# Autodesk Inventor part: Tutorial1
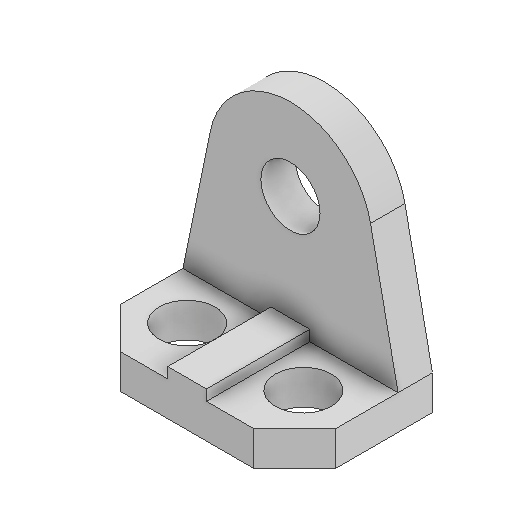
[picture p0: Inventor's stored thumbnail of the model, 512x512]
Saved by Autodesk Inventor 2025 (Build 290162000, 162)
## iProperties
Created: 2021-03
Part Number: Tutorial1
Material: Generic
Document SubType Name: Modeling
Designer: ASUS Laptop
Density: 1 g/cm^3
Appearance: Default
Author: ASUS Laptop
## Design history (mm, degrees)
sketch "Sketch1"
  geometry: L1 (0, 0)-(-200, 0); L2 (-200, 0)-(-200, 90); L3 (-200, 90)-(-162, 128); L4 (-162, 128)-(-38, 128); L5 (-38, 128)-(0, 90); L6 (0, 90)-(0, 0); L7 (-154, 74)-(-31.817, 74); C1 r 26 at (-154, 74); C2 r 26 at (-46, 74); 1 further point
  constraints: 14 end point, 2 centre point, 2 horizontal, 2 parallel, 2 perpendicular, 1 coincident, 1 equal radius, 1 point on line
  dimensions: "d0" = 128 distance between parallel lines of L4 L1; "d1" = 90 distance of L1.end L2.end; "d2" = 124 distance of L3.end L4.end; "d3" = 38 horizontal distance of L3.end L2.end; "d4" = 38 horizontal distance of L5.end L4.end; "d5" = 46 distance from line of L7.start L2; "d6" = 46 distance from line of L6 C2.centre; "d7" = 74 distance from line of L7.start L1; "d8" = 52 diameter of C2
extrude "Extrusion1" new body sketch "Sketch1" distance "d9" = 32; taper "d10" = 0 deg
sketch "Sketch2"
  geometry: L1 (200, 32)-(162, 32) reference; L2 (200, 32)-(174.418, 155.424); L3 (38, 32)-(0, 32) reference; L4 (25.582, 155.424)-(0, 32); L5 (0, 32)-(200, 32); L6 (162, 0)-(38, 0) reference; L7 (100, 0)-(100, 176.194); C1 r 27.5 at (100, 140); A1 r 76 centre (100, 140) between (174.418, 155.424) and (25.582, 155.424); 3 further points
  constraints: 8 end point, 2 centre point, 2 point on circle, 2 tangent, 1 coincident, 1 collinear, 1 midpoint, 1 vertical, 1 other
  dimensions: "d11" = 76 radius of A1; "d12" = 108 distance from line of A1.centre L5; "d13" = 55 diameter of C1
extrude "Extrusion2" join sketch "Sketch2" distance "d14" = 32; taper "d15" = 0 deg
sketch "Sketch4"
  geometry: L1 (0, 32)-(124, 32) reference; L2 (44, 32)-(80, 32); L3 (80, 32)-(80, 42); L4 (80, 42)-(44, 42); L5 (44, 42)-(44, 32); L6 (-38, 0)-(-38, 32) reference; 1 further point
  constraints: 8 end point, 2 parallel, 1 horizontal, 1 perpendicular, 1 point on line
  dimensions: "d16" = 36 distance of L3.end L4.end; "d17" = 10 distance of L4.end L2.start; "d18" = 82 distance between parallel lines of L5 L6
extrude "Extrusion3" join sketch "Sketch4" stored distance "d19" = 32; taper "d20" = 0 deg
body "Solid1"
sketch "Sketch3"
  geometry: 1 further point
